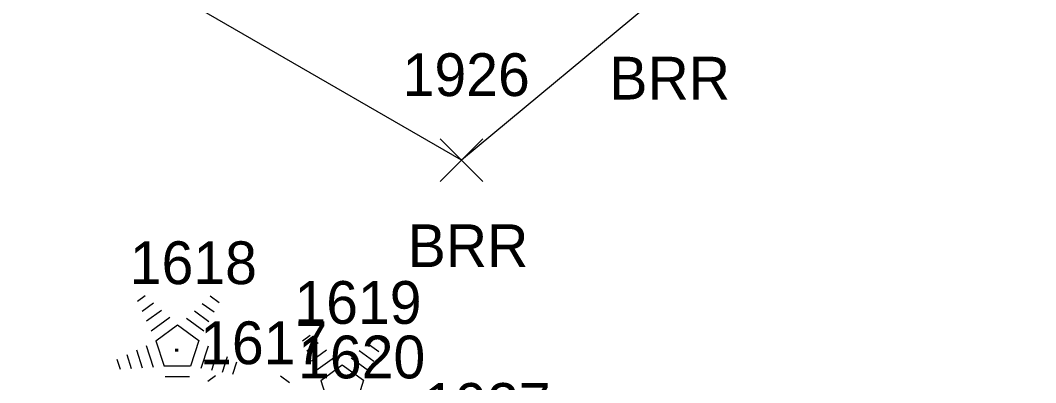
# Model space of a CAD drawing. Extents: x 1499292 to 1501024, y 534584 to 538043.
# Drawn here: x 1499887.83 to 1499935.33, y 537661.49 to 537678.44 of the extents above; entities that cross this region are included whole.
import ezdxf

# ---------------------------------------------------------------- set-up
doc = ezdxf.new("R2010")
doc.units = 0
for name, color, linetype in [('L_A', 7, 'Continuous'), ('L_I', 7, 'Continuous'), ('L_TIC', 7, 'Continuous'), ('LABL', 7, 'Continuous'), ('LTC', 7, 'Continuous')]:
    doc.layers.add(name, color=color, linetype=linetype)

msp = doc.modelspace()

# ---------------------------------------------------------------- linework, layer by layer
at = {"layer": 'L_TIC'}
for points in [[(1499907.462, 537670.894), (1499909.462, 537672.894)], [(1499909.462, 537670.894), (1499907.462, 537672.894)]]:
    msp.add_lwpolyline(points, dxfattribs=at)
at = {"layer": 'LABL'}
msp.add_lwpolyline([(1499985.467, 537801.862), (1499975.641, 537783.145), (1499970.041, 537762.697), (1499961.498, 537757.027), (1499956.574, 537742.207), (1499948.778, 537731.888), (1499940.204, 537717.909), (1499933.775, 537706.198), (1499925.612, 537690.188), (1499917.898, 537679.732), (1499908.462, 537671.894), (1499888.043, 537683.7), (1499880.149, 537690.561), (1499889.261, 537696.2)], dxfattribs=at)
at = {"layer": 'LTC'}
for p, q in [((1499893.315, 537665.306), (1499893.67, 537665.563)), ((1499896.713, 537665.546), (1499897.132, 537665.242)), ((1499893.525, 537664.841), (1499894.054, 537665.225)), ((1499896.342, 537665.198), (1499896.892, 537664.799)), ((1499893.734, 537664.375), (1499894.438, 537664.886)), ((1499893.944, 537663.909), (1499894.822, 537664.547)), ((1499895.971, 537664.85), (1499896.65, 537664.356)), ((1499894.168, 537663.454), (1499895.18, 537664.188)), ((1499895.18, 537664.188), (1499896.177, 537663.463)), ((1499895.6, 537664.501), (1499896.41, 537663.913)), ((1499901.026, 537663.449), (1499901.38, 537663.706)), ((1499904.424, 537663.689), (1499904.843, 537663.385)), ((1499893.714, 537663.235), (1499894.045, 537662.216)), ((1499894.168, 537663.454), (1499894.555, 537662.261)), ((1499896.177, 537663.463), (1499895.786, 537662.261)), ((1499896.615, 537663.193), (1499896.277, 537662.153)), ((1499901.235, 537662.983), (1499901.764, 537663.368)), ((1499904.053, 537663.341), (1499904.602, 537662.942)), ((1499892.803, 537662.802), (1499893.015, 537662.15)), ((1499893.258, 537663.018), (1499893.53, 537662.183)), ((1499897.059, 537662.942), (1499896.772, 537662.058)), ((1499897.504, 537662.692), (1499897.267, 537661.963)), ((1499901.445, 537662.518), (1499902.149, 537663.029)), ((1499901.654, 537662.052), (1499902.533, 537662.69)), ((1499903.311, 537662.644), (1499904.12, 537662.055)), ((1499903.682, 537662.993), (1499904.361, 537662.499)), ((1499892.347, 537662.585), (1499892.5, 537662.117)), ((1499895.786, 537662.261), (1499894.555, 537662.261)), ((1499897.948, 537662.442), (1499897.761, 537661.868)), ((1499901.879, 537661.597), (1499902.891, 537662.331)), ((1499902.891, 537662.331), (1499903.888, 537661.606)), ((1499895.747, 537661.761), (1499894.603, 537661.761)), ((1499896.606, 537661.562), (1499896.961, 537661.82)), ((1499900.005, 537661.802), (1499900.424, 537661.498)), ((1499901.879, 537661.597), (1499902.266, 537660.403)), ((1499903.888, 537661.606), (1499903.497, 537660.403))]:
    msp.add_line(p, q, dxfattribs=at)

# ---------------------------------------------------------------- texts
at = {"layer": 'L_A'}
for p in [(1499915.386, 537674.732), (1499905.95, 537666.894)]:
    msp.add_text('BRR', height=2, dxfattribs=at).set_placement(p)
at = {"layer": 'L_I'}
for s, p in [('1926', (1499905.714, 537674.894)), ('1618', (1499892.947, 537666.098)), ('1619', (1499900.649, 537664.241)), ('1617', (1499896.238, 537662.354)), ('1620', (1499900.821, 537661.691)), ('1927', (1499906.687, 537659.471))]:
    msp.add_text(s, height=2, dxfattribs=at).set_placement(p)
at = {"layer": 'LTC'}
msp.add_text('.', height=1.037, rotation=270, dxfattribs=at).set_placement((1499895.062, 537663.202))

doc.saveas('drawing.dxf')
